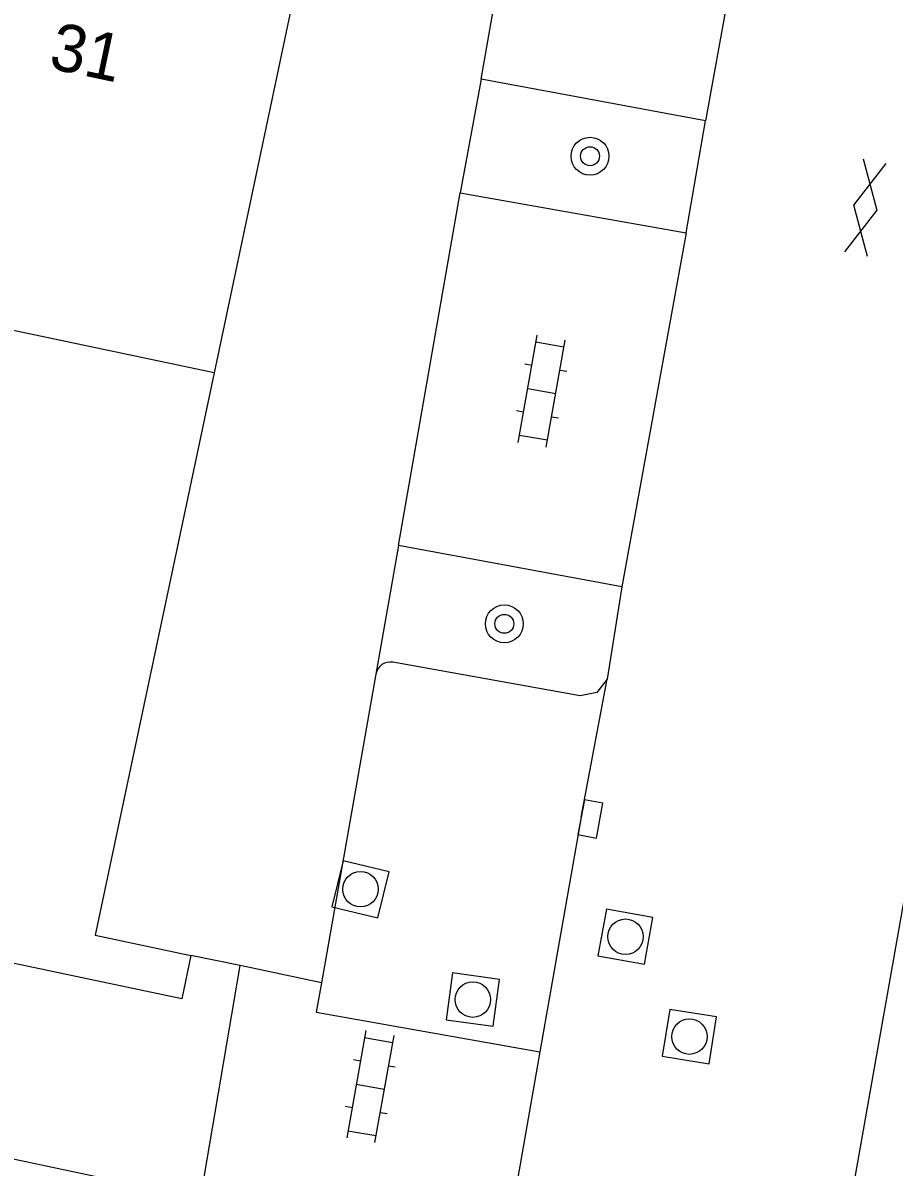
# Model space of a CAD drawing. Extents: x 131000 to 133013, y 393000 to 396501.
# Drawn here: x 131740.18 to 131758.58, y 393516.28 to 393540.46 of the extents above; entities that cross this region are included whole.
import ezdxf

# ---------------------------------------------------------------- set-up
doc = ezdxf.new("R2010")
doc.units = 0
for name, color, linetype in [('gg-anno-huisnummerreeks BGT', 7, 'Continuous'), ('gg-bbg-hoofdgebouw', 7, 'Continuous'), ('gg-bbg-tussenscheiding', 7, 'Continuous'), ('gg-knt-verharding', 7, 'Continuous'), ('gg-knt-verharding nz', 7, 'Continuous'), ('gt-grn-vlakafsluiter', 7, 'Continuous'), ('gt-grn-weggrens', 7, 'Continuous'), ('gt-symb-boom', 7, 'Continuous'), ('gt-symb-gesloten verharding', 7, 'Continuous'), ('gt-symb-klinker verharding', 7, 'Continuous'), ('gt-symb-kolk', 7, 'Continuous'), ('gt-symb-rioolschacht', 7, 'Continuous')]:
    doc.layers.add(name, color=color, linetype=linetype)

# ---------------------------------------------------------------- blocks, each defined once
blk = doc.blocks.new('gt0-GESVH1')
at = {"layer": 'gt-symb-gesloten verharding'}
for p, q in [((-0.992, -0.261), (0.008, 0.239)), ((0.008, -0.261), (-0.992, 0.239)), ((0.008, 0.239), (1.008, -0.261)), ((1.008, 0.239), (0.008, -0.261))]:
    blk.add_line(p, q, dxfattribs=at)
blk = doc.blocks.new('gt0-KL1')
at = {"layer": 'gt-symb-klinker verharding'}
for p, q in [((-1.15, 0.3), (1.15, 0.3)), ((-1, -0.3), (-1, 0.3)), ((-0.5, 0.3), (-0.5, 0.45)), ((0, -0.3), (0, 0.3)), ((0.5, 0.3), (0.5, 0.45)), ((1, -0.3), (1, 0.3)), ((-1.15, -0.3), (1.15, -0.3)), ((-0.5, -0.45), (-0.5, -0.3)), ((0.5, -0.45), (0.5, -0.3))]:
    blk.add_line(p, q, dxfattribs=at)
blk = doc.blocks.new('gt0-BOOM')
at = {"layer": 'gt-symb-boom'}
for radius in [0.4, 0.2]:
    blk.add_circle((0, 0), radius, dxfattribs=at)
blk = doc.blocks.new('gt0-RS')
at = {"layer": 'gt-symb-rioolschacht'}
blk.add_lwpolyline([(-0.5, -0.5), (0.5, -0.5), (0.5, 0.5), (-0.5, 0.5)], close=True, dxfattribs=at)
blk.add_circle((0, 0), 0.375, dxfattribs=at)
blk = doc.blocks.new('gt0-KOLK')
at = {"layer": 'gt-symb-kolk'}
blk.add_lwpolyline([(0, 0), (0.375, 0), (0.375, 0.4), (-0.375, 0.4), (-0.375, 0), (0, 0)], dxfattribs=at)

msp = doc.modelspace()

# ---------------------------------------------------------------- linework, layer by layer
at = {"layer": 'gg-bbg-hoofdgebouw'}
msp.add_line((131743.095, 393515.79), (131712.284, 393522.311), dxfattribs=at)
for points in [[(131718.534, 393551.875), (131748.963, 393545.431), (131748.759, 393544.517), (131746.728, 393544.951), (131744.215, 393533.066)], [(131744.215, 393533.066), (131741.703, 393521.18), (131743.726, 393520.756)], [(131743.726, 393520.756), (131743.533, 393519.839), (131713.133, 393526.248)]]:
    msp.add_lwpolyline(points, dxfattribs=at)
at = {"layer": 'gg-bbg-tussenscheiding'}
msp.add_line((131744.215, 393533.066), (131715.834, 393539.061), dxfattribs=at)
at = {"layer": 'gg-knt-verharding'}
for p, q in [((131749.857, 393539.267), (131751.164, 393546.723)), ((131755.96, 393545.921), (131754.599, 393538.387)), ((131754.599, 393538.387), (131749.857, 393539.267)), ((131754.189, 393536.023), (131754.599, 393538.387)), ((131748.113, 393529.416), (131749.417, 393536.872)), ((131749.417, 393536.872), (131754.189, 393536.023)), ((131754.189, 393536.023), (131752.83, 393528.541)), ((131752.83, 393528.541), (131748.113, 393529.416)), ((131752.83, 393528.541), (131752.524, 393526.59)), ((131747.635, 393526.701), (131746.484, 393520.178)), ((131751.97, 393523.677), (131752.524, 393526.59)), ((131751.97, 393523.677), (131751.101, 393518.72)), ((131744.766, 393520.538), (131743.726, 393520.756)), ((131746.484, 393520.178), (131744.766, 393520.538)), ((131751.101, 393518.72), (131749.824, 393511.432))]:
    msp.add_line(p, q, dxfattribs=at)
for points in [[(131772.935, 393601.922), (131753.053, 393489.505), (131752.976, 393489.244)], [(131752.524, 393526.59), (131752.301, 393526.309), (131751.952, 393526.241), (131747.995, 393526.949)]]:
    msp.add_lwpolyline(points, dxfattribs=at)
msp.add_arc((131747.94, 393526.644), 0.31, 79.7176, 169.4074, dxfattribs=at)
at = {"layer": 'gg-knt-verharding nz'}
msp.add_lwpolyline([(131746.484, 393520.178), (131746.374, 393519.556), (131751.101, 393518.72)], dxfattribs=at)
at = {"layer": 'gt-grn-vlakafsluiter'}
for p, q in [((131749.857, 393539.267), (131749.417, 393536.872)), ((131748.113, 393529.416), (131747.635, 393526.701))]:
    msp.add_line(p, q, dxfattribs=at)
at = {"layer": 'gt-grn-weggrens'}
msp.add_line((131743.931, 393515.615), (131744.766, 393520.538), dxfattribs=at)

# ---------------------------------------------------------------- block references
at = {"layer": 'gt-symb-boom'}
for p in [(131752.159, 393537.642), (131750.349, 393527.761)]:
    msp.add_blockref('gt0-BOOM', p, dxfattribs=at)
at = {"layer": 'gt-symb-gesloten verharding', "rotation": -101.4223210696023}
msp.add_blockref('gt0-GESVH1', (131757.988, 393536.561), dxfattribs=at)
at = {"layer": 'gt-symb-klinker verharding'}
for p, rotation in [((131751.139, 393532.676), 79.98206552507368), ((131747.515, 393517.983), -100.07433273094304)]:
    msp.add_blockref('gt0-KL1', p, dxfattribs=dict(at, rotation=rotation))
at = {"layer": 'gt-symb-kolk', "rotation": -100.71464389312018}
msp.add_blockref('gt0-KOLK', (131751.97, 393523.677), dxfattribs=at)
at = {"layer": 'gt-symb-rioolschacht'}
for p, rotation in [((131747.31, 393522.153), -13.480126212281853), ((131752.908, 393521.149), 79.80279442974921), ((131749.683, 393519.821), 172.24257421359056), ((131754.259, 393519.039), 80.90519501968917)]:
    msp.add_blockref('gt0-RS', p, dxfattribs=dict(at, rotation=rotation))

# ---------------------------------------------------------------- texts
at = {"layer": 'gg-anno-huisnummerreeks BGT'}
msp.add_text('31', height=1, rotation=348.1, dxfattribs=at).set_placement((131740.695, 393539.507))

doc.saveas('drawing.dxf')
